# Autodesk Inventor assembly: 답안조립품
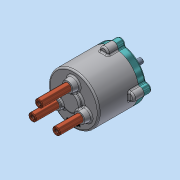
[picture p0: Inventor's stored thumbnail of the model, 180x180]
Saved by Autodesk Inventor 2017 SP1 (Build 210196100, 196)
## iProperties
Part Number: 답안조립품
Material: 일반
Document SubType Name: Assembly
Designer: MRC
Author: MRC
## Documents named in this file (14)
- C:\Users\MRC\Desktop\610708V1011\답안조립품.iam
- C:\Users\MRC\Desktop\610708V1011\본체.ipt
- C:\Users\MRC\Desktop\610708V1011\가변스프링1.ipt
- C:\Users\MRC\Desktop\610708V1011\가변스프링2.ipt
- C:\Users\MRC\Desktop\610708V1011\가변스프링3.ipt
- C:\Users\MRC\Desktop\610708V1011\멈춤링 10 x 1.ipt
- C:\Users\MRC\Desktop\610708V1011\멈춤링 22 x 1.2.ipt
- C:\Users\MRC\Desktop\610708V1011\메인 축.ipt
- C:\Users\MRC\Desktop\610708V1011\베어링 NA 4900.ipt
- C:\Users\MRC\Desktop\610708V1011\볼트 M5.ipt
- C:\Users\MRC\Desktop\610708V1011\슬라이드 축.ipt
- C:\Users\MRC\Desktop\610708V1011\오일실.ipt
- C:\Users\MRC\Desktop\610708V1011\커버.ipt
- C:\Users\MRC\Desktop\610708V1011\판캠.ipt
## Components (3 placed, 3 different names)
1. 가변스프링1:1
2. 가변스프링2:1
3. 가변스프링3:1
